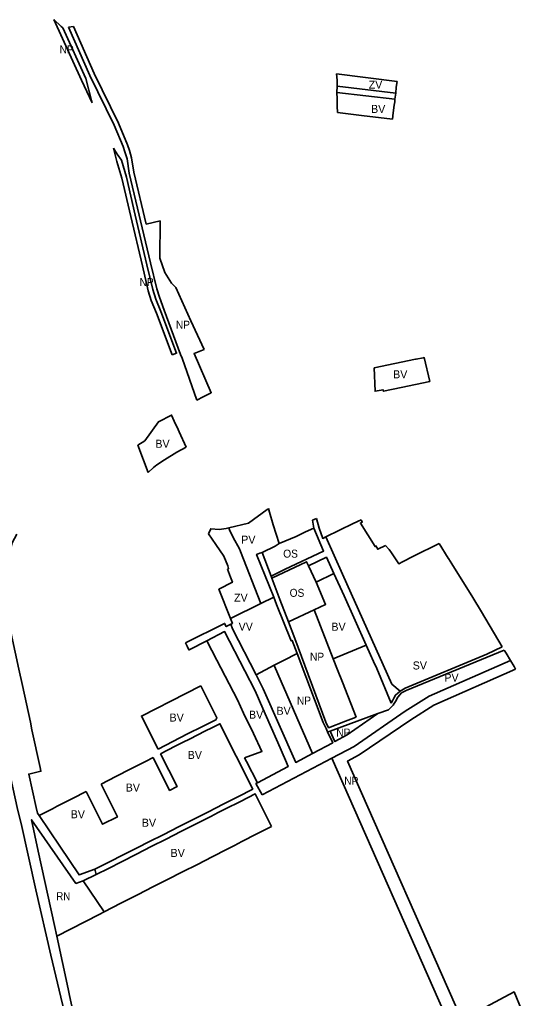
# Model space of a CAD drawing. Extents: x -650971 to -642489, y -1074311 to -1062745.
# Drawn here: x -648725 to -647975, y -1068126 to -1066658 of the extents above; entities that cross this region are included whole.
import ezdxf

# ---------------------------------------------------------------- set-up
doc = ezdxf.new("R2010")
doc.units = 0
doc.header["$LTSCALE"] = 4.8
for name, color, linetype, lineweight in [('15', 7, 'Continuous', 35), ('19', 7, 'Continuous', 35), ('3', 7, 'Continuous', 35), ('40', 7, 'Continuous', 35), ('45', 7, 'Continuous', 35), ('48', 7, 'Continuous', 35), ('62', 7, 'Continuous', 35), ('7', 7, 'Continuous', 35), ('9', 7, 'Continuous', 35)]:
    doc.layers.add(name, color=color, linetype=linetype, lineweight=lineweight)

msp = doc.modelspace()

# ---------------------------------------------------------------- linework, layer by layer
at = {"layer": '15'}
msp.add_lwpolyline([(-648248.77, -1066767.43), (-648248.43, -1066758.34), (-648160.51, -1066768.4), (-648161.58, -1066777.41)], close=True, dxfattribs=at)
for points in [[(-648410.92, -1067420.63), (-648381.48, -1067413.68), (-648353.35, -1067393.29), (-648352.16, -1067392.42), (-648351.06, -1067391.62)], [(-648351.06, -1067391.62), (-648349.67, -1067396.88), (-648344.41, -1067416.04), (-648335.38, -1067444.07)], [(-648347.51, -1067492.87), (-648326.09, -1067482.7), (-648268.67, -1067455.43), (-648283.21, -1067420.88), (-648285.08, -1067409.24), (-648279.24, -1067406.38)], [(-648279.24, -1067406.38), (-648275.41, -1067421.3), (-648270.02, -1067436.37), (-648265.197, -1067434.03)], [(-648362.585, -1067534.204), (-648393.17, -1067455.88), (-648394.92, -1067452.23), (-648404.29, -1067434.9), (-648409.61, -1067423.44), (-648410.92, -1067420.63)], [(-648728.95, -1067430.33), (-648735.59, -1067442.88), (-648748.53, -1067499.3), (-648751.29, -1067514.57), (-648731.06, -1067607.06), (-648725.8, -1067632.36), (-648720.1, -1067657.12), (-648708.26, -1067712.07), (-648706.08, -1067723.56)], [(-648265.197, -1067434.03), (-648240.51, -1067489.9), (-648166.173, -1067654.853), (-648153.98, -1067665.43)], [(-648335.38, -1067444.07), (-648341.15, -1067448.14), (-648361, -1067457.36), (-648364.19, -1067458.619)], [(-648580.062, -1068590.087), (-648579.97, -1068587.39), (-648566.33, -1068582.22), (-648561.032, -1068578.982), (-648572.95, -1068522.97), (-648573.96, -1068518.34), (-648594.38, -1068425.02), (-648615.87, -1068327.3), (-648634.84, -1068248.76), (-648655.88, -1068153.63), (-648662.71, -1068124.76), (-648677.61, -1068061.74), (-648700.16, -1067963.42), (-648722.09, -1067863.84), (-648727.05, -1067844.33), (-648738.7, -1067792.04), (-648749.97, -1067741.49), (-648767.84, -1067652.98), (-648791.68, -1067543.78), (-648792.97, -1067537.86), (-648804.08, -1067534.88), (-648813.94, -1067506.27), (-648827.86, -1067465.86)], [(-648364.19, -1067458.619), (-648369.01, -1067460.52), (-648343.409, -1067524.81), (-648362.585, -1067534.204)], [(-648253.1, -1067489.23), (-648264.34, -1067464.83), (-648291.17, -1067477.57)], [(-648291.17, -1067477.57), (-648291.172, -1067477.571), (-648294.04, -1067471.35), (-648346.27, -1067496.14), (-648347.51, -1067492.87)], [(-648204.88, -1067596.54), (-648237.81, -1067522.42), (-648253.1, -1067489.23)], [(-648475.78, -1067593.11), (-648417.19, -1067564.02), (-648414.73, -1067568.8), (-648408.002, -1067565.219)], [(-648408.002, -1067565.219), (-648405.054, -1067571.837), (-648369.949, -1067640.851)], [(-648367.811, -1067802.994), (-648321.623, -1067778.399), (-648326, -1067769), (-648337.32, -1067742.59), (-648348.55, -1067716.71), (-648359.6, -1067691.58), (-648371.34, -1067665.08), (-648386.91, -1067634.83), (-648417.12, -1067576.17), (-648443.83, -1067589.92), (-648470.47, -1067603.64)], [(-648470.47, -1067603.64), (-648470.57, -1067603.69), (-648473.34, -1067598.06), (-648475.78, -1067593.11)], [(-648167.48, -1067683.45), (-648189.03, -1067631.71), (-648193.8, -1067621), (-648198.39, -1067610.97), (-648204.88, -1067596.54)], [(-648187.139, -1067699.179), (-648171.21, -1067693.37), (-648164.09, -1067686.51), (-648162.69, -1067684), (-648161, -1067680.96), (-648157.2, -1067674.32), (-648151.6, -1067668.12), (-648144.83, -1067664.48), (-647997.681, -1067604.11)], [(-647997.681, -1067604.11), (-647995.04, -1067608.56), (-647988.334, -1067619.747)], [(-647988.334, -1067619.747), (-648110.36, -1067673.133), (-648146.127, -1067695.8), (-648222.872, -1067748.412), (-648256.499, -1067766.091), (-648360.993, -1067821.027)], [(-648369.949, -1067640.851), (-648359.213, -1067661.956), (-648310.511, -1067772.476), (-648285.254, -1067759.009)], [(-648153.98, -1067665.43), (-648160.68, -1067671.55), (-648163.11, -1067676.17), (-648164.79, -1067678.96), (-648167.48, -1067683.45)], [(-648258.96, -1067725.37), (-648251.711, -1067741.124), (-648233.264, -1067731.288), (-648187.139, -1067699.179)], [(-648706.08, -1067723.56), (-648693.78, -1067780.24), (-648692.53, -1067785.79), (-648704.614, -1067788.491), (-648710.96, -1067789.91), (-648699.593, -1067840.046)], [(-648285.254, -1067759.009), (-648255.016, -1067742.886), (-648262.632, -1067726.711), (-648262.63, -1067726.71), (-648258.96, -1067725.37)], [(-648360.993, -1067821.027), (-648370.113, -1067804.22), (-648367.811, -1067802.994)], [(-648699.593, -1067840.046), (-648699.621, -1067840.06), (-648697.7, -1067848.43), (-648695.27, -1067852.04)], [(-648629.22, -1067950.214), (-648640, -1067954), (-648706.687, -1067858.345), (-648696.93, -1067905.76), (-648672.31, -1068017.25), (-648668.92, -1068032.96)], [(-648695.27, -1067852.04), (-648664.41, -1067897.91), (-648635.249, -1067941.252), (-648611.61, -1067932.63), (-648609.91, -1067940.58), (-648629.22, -1067950.214)], [(-648668.92, -1068032.96), (-648651.89, -1068111.95), (-648649.74, -1068121.95), (-648644.73, -1068145.27), (-648630.99, -1068209.19), (-648610.14, -1068304.32), (-648587.39, -1068405.82), (-648559.91, -1068532.62), (-648551.041, -1068573.16)]]:
    msp.add_lwpolyline(points, dxfattribs=at)
at = {"layer": '19'}
for points in [[(-648265.197, -1067434.03), (-648224.19, -1067414.14), (-648212.32, -1067408.39)], [(-648212.32, -1067408.39), (-648211.08, -1067410.6), (-648210.48, -1067411.68), (-648213.34, -1067413.46), (-648191.46, -1067448.59), (-648190.23, -1067447.83), (-648187.44, -1067452.8), (-648175.94, -1067446.89)], [(-648153.98, -1067665.43), (-648166.173, -1067654.853), (-648240.51, -1067489.9), (-648265.197, -1067434.03)], [(-648175.94, -1067446.89), (-648171.21, -1067452.01), (-648170.38, -1067453.23), (-648166.97, -1067458.18), (-648155.85, -1067474.35), (-648150.46, -1067471.66)], [(-648150.46, -1067471.66), (-648133.56, -1067463.2), (-648095.28, -1067444.06)], [(-648095.28, -1067444.06), (-648081.69, -1067465.92), (-648081.31, -1067466.54), (-648076.32, -1067474.6), (-648045.04, -1067525.15), (-648031.77, -1067546.6), (-648000.63, -1067599.14)], [(-648000.63, -1067599.14), (-648023.96, -1067610.13), (-648146.21, -1067661.3), (-648153.98, -1067665.43)]]:
    msp.add_lwpolyline(points, dxfattribs=at)
at = {"layer": '3'}
for p, q in [((-648248.77, -1066767.43), (-648161.58, -1066777.41)), ((-648369.949, -1067640.851), (-648342.697, -1067626.806)), ((-648629.22, -1067950.214), (-648609.91, -1067940.58))]:
    msp.add_line(p, q, dxfattribs=at)
for points in [[(-648247.78, -1066797.53), (-648248.09, -1066787.96), (-648248.448, -1066777.212), (-648248.77, -1066767.43)], [(-648161.58, -1066777.41), (-648162.01, -1066781.79), (-648162.8, -1066786.8), (-648164.14, -1066797.98), (-648165.33, -1066807.74)], [(-648165.33, -1066807.74), (-648211.58, -1066802.18), (-648247.78, -1066797.53)], [(-648193.02, -1067180.66), (-648131.01, -1067167.84), (-648130.21, -1067167.7), (-648118.74, -1067165.43), (-648117.563, -1067165.191), (-648109.1, -1067201.21)], [(-648109.1, -1067201.21), (-648152.5, -1067210.23), (-648179, -1067215.71), (-648179.42, -1067213.37), (-648191.439, -1067215.62), (-648193.02, -1067180.66)], [(-648531.51, -1067337.57), (-648547.17, -1067296.68), (-648536.84, -1067290.29), (-648516.47, -1067261.54), (-648496.55, -1067251.53), (-648492.62, -1067260.53)], [(-648492.62, -1067260.53), (-648486.79, -1067273.26), (-648485.16, -1067276.83), (-648474.69, -1067299.66)], [(-648474.69, -1067299.66), (-648488.66, -1067307.11), (-648507.25, -1067318.35), (-648518.55, -1067326.3), (-648523.55, -1067330.33), (-648531.51, -1067337.57)], [(-648282.863, -1067543.596), (-648265.757, -1067535.555), (-648279.86, -1067502.11), (-648253.1, -1067489.23)], [(-648253.1, -1067489.23), (-648237.81, -1067522.42), (-648204.88, -1067596.54), (-648254.04, -1067616.96), (-648282.863, -1067543.596)], [(-648443.83, -1067589.92), (-648417.12, -1067576.17), (-648386.91, -1067634.83), (-648371.34, -1067665.08), (-648359.6, -1067691.58), (-648348.55, -1067716.71), (-648337.32, -1067742.59), (-648326, -1067769), (-648321.623, -1067778.399), (-648367.811, -1067802.994)], [(-648387.04, -1067765.67), (-648361.08, -1067755.88), (-648373.99, -1067728.95), (-648388.506, -1067698.645), (-648397.98, -1067678.79), (-648428.7, -1067619.24), (-648443.83, -1067589.92)], [(-648342.697, -1067626.806), (-648342.023, -1067628.096), (-648285.254, -1067759.009)], [(-648285.254, -1067759.009), (-648310.511, -1067772.476), (-648359.213, -1067661.956), (-648369.949, -1067640.851)], [(-648516.73, -1067752.57), (-648541.86, -1067702.86), (-648475.01, -1067668.94), (-648452.72, -1067657.62)], [(-648452.72, -1067657.62), (-648428.67, -1067705.52), (-648430.17, -1067708.33), (-648450.23, -1067718.32), (-648472.5, -1067729.76), (-648494.84, -1067741.06), (-648516.73, -1067752.57)], [(-648513.23, -1067759.38), (-648491.14, -1067748.02), (-648480.06, -1067742.47), (-648468.97, -1067736.91), (-648446.58, -1067725.71), (-648435.34, -1067720.01), (-648424.14, -1067714.34), (-648399.64, -1067763.26), (-648374.84, -1067812.43), (-648397.04, -1067823.85), (-648419.44, -1067835.3), (-648441.47, -1067846.37), (-648486.09, -1067868.98), (-648508.22, -1067880.38), (-648530.81, -1067891.61), (-648547.09, -1067899.87), (-648611.61, -1067932.63)], [(-648524.44, -1067765.11), (-648499.7, -1067814.37), (-648488.49, -1067808.76), (-648513.23, -1067759.38)], [(-648602.3, -1067804.83), (-648580.14, -1067793.61), (-648557.84, -1067782.26), (-648535.61, -1067770.85), (-648524.44, -1067765.11)], [(-648367.811, -1067802.994), (-648384.25, -1067771.07), (-648387.04, -1067765.67)], [(-648695.27, -1067852.04), (-648675.26, -1067841.84), (-648668.085, -1067838.186), (-648658.42, -1067833.26), (-648645.11, -1067826.48), (-648624.76, -1067816.11)], [(-648624.76, -1067816.11), (-648600.14, -1067865.29), (-648577.78, -1067854.07), (-648602.3, -1067804.83)], [(-648609.91, -1067940.58), (-648591.04, -1067931.62), (-648571.88, -1067921.71), (-648549.44, -1067910.07), (-648527.33, -1067898.74), (-648504.92, -1067887.52), (-648482.5, -1067876.22), (-648437.89, -1067853.4), (-648426.65, -1067847.64), (-648415.69, -1067841.98), (-648393.35, -1067830.81), (-648371.27, -1067819.47), (-648346.57, -1067868.56)], [(-648611.61, -1067932.63), (-648635.249, -1067941.252), (-648664.41, -1067897.91), (-648695.27, -1067852.04)], [(-648346.57, -1067868.56), (-648368.78, -1067879.75), (-648391.08, -1067891.24), (-648402.29, -1067897.02), (-648413.41, -1067902.53), (-648435.55, -1067913.84), (-648457.87, -1067925.4), (-648480.12, -1067936.55), (-648502.59, -1067948), (-648524.72, -1067958.93), (-648546.76, -1067970.44), (-648572.5, -1067983.59), (-648597.93, -1067996.72), (-648629.22, -1067950.214)]]:
    msp.add_lwpolyline(points, dxfattribs=at)
at = {"layer": '40'}
msp.add_line((-648249.44, -1066739.8), (-648158.49, -1066750.93), dxfattribs=at)
for points in [[(-648248.43, -1066758.34), (-648248.34, -1066749.33), (-648249.44, -1066739.8)], [(-648158.49, -1066750.93), (-648159.66, -1066759.8), (-648160.51, -1066768.4), (-648248.43, -1066758.34)], [(-648441.48, -1067429.63), (-648437.75, -1067421.99), (-648425, -1067423.05), (-648414.84, -1067421.56), (-648410.92, -1067420.63)], [(-648410.92, -1067420.63), (-648409.61, -1067423.44), (-648404.29, -1067434.9), (-648394.92, -1067452.23), (-648393.17, -1067455.88), (-648362.585, -1067534.204), (-648408.26, -1067556.58)], [(-648418.3, -1067462.86), (-648430.4, -1067445.51), (-648441.48, -1067429.63)], [(-648412.89, -1067482.55), (-648411.25, -1067481.73), (-648412.46, -1067477.42), (-648418.3, -1067462.86)], [(-648408.26, -1067556.58), (-648425.5, -1067512.73), (-648405.27, -1067502.27), (-648408.24, -1067494.59), (-648412.89, -1067482.55)]]:
    msp.add_lwpolyline(points, dxfattribs=at)
at = {"layer": '45'}
for points in [[(-648408.26, -1067556.58), (-648362.585, -1067534.205), (-648343.409, -1067524.81)], [(-648343.409, -1067524.81), (-648339.16, -1067535.48), (-648317.43, -1067590), (-648315.92, -1067589.37), (-648308.43, -1067609.15)], [(-648408.002, -1067565.219), (-648405.41, -1067563.84), (-648408.26, -1067556.58)], [(-648369.949, -1067640.851), (-648405.054, -1067571.837), (-648408.002, -1067565.219)], [(-648308.43, -1067609.15), (-648328.54, -1067619.51), (-648342.697, -1067626.806), (-648369.949, -1067640.851)]]:
    msp.add_lwpolyline(points, dxfattribs=at)
at = {"layer": '48'}
for p, q in [((-648651.1, -1066669.56), (-648643.925, -1066668.483)), ((-648258.96, -1067725.37), (-648187.139, -1067699.179))]:
    msp.add_line(p, q, dxfattribs=at)
for points in [[(-648673.407, -1066658.275), (-648662.46, -1066668.53), (-648659.95, -1066670.89), (-648625.44, -1066746.45)], [(-648615.972, -1066783.008), (-648631.791, -1066749.394), (-648673.407, -1066658.275)], [(-648458.73, -1067229.1), (-648480.57, -1067166.13), (-648483.31, -1067160.63), (-648507.88, -1067093.9), (-648514.86, -1067074.83), (-648518.72, -1067061.99), (-648528.01, -1067023.13), (-648560.2, -1066888.58), (-648563.48, -1066866.96), (-648566.63, -1066856.72), (-648569.13, -1066848.61), (-648582.52, -1066816.7), (-648619.11, -1066742.12), (-648651.1, -1066669.56)], [(-648643.925, -1066668.483), (-648612.763, -1066739.165), (-648576.145, -1066813.802), (-648562.542, -1066846.219), (-648559.94, -1066854.66), (-648556.637, -1066865.397), (-648553.323, -1066887.238), (-648534.701, -1066965.077), (-648513.842, -1066960.243)], [(-648625.44, -1066746.45), (-648616.86, -1066779.79), (-648615.972, -1066783.008)], [(-648583.94, -1066851.11), (-648577.99, -1066860.17), (-648571.96, -1066869.37)], [(-648495.63, -1067161.363), (-648519.471, -1067098.516), (-648526.988, -1067079.8), (-648531.681, -1067065.222), (-648540.476, -1067027.594), (-648557.816, -1066953.444), (-648571.167, -1066896.326), (-648578.702, -1066871.259), (-648583.94, -1066851.11)], [(-648571.96, -1066869.37), (-648564.4, -1066894.52), (-648551, -1066951.85), (-648533.66, -1067026), (-648524.93, -1067063.35), (-648520.4, -1067077.42), (-648512.95, -1067095.97), (-648489.1, -1067158.84), (-648495.63, -1067161.363)], [(-648513.842, -1066960.243), (-648514.38, -1067016.2), (-648506.78, -1067037.81), (-648496.87, -1067053.5), (-648490.23, -1067060.06), (-648467.56, -1067110.02), (-648447.66, -1067153.25)], [(-648447.66, -1067153.25), (-648462.97, -1067159.24), (-648437.02, -1067217.99), (-648449.03, -1067224.14), (-648458.73, -1067229.1)], [(-648321.361, -1067561.69), (-648282.863, -1067543.596), (-648254.04, -1067616.96)], [(-648219.86, -1067704.42), (-648235.78, -1067710.79), (-648261.25, -1067720.39), (-648265.08, -1067712.06), (-648311.95, -1067586.45), (-648321.361, -1067561.69)], [(-648342.697, -1067626.806), (-648328.54, -1067619.51), (-648308.43, -1067609.15)], [(-648308.43, -1067609.15), (-648269.27, -1067712.6), (-648264.949, -1067721.79), (-648262.63, -1067726.71)], [(-648285.254, -1067759.009), (-648342.023, -1067628.096), (-648342.697, -1067626.806)], [(-648256.499, -1067766.091), (-648222.872, -1067748.412), (-648146.127, -1067695.8), (-648110.36, -1067673.133), (-647988.334, -1067619.747)], [(-648254.04, -1067616.96), (-648247.53, -1067633.53), (-648240.19, -1067652.12), (-648219.86, -1067704.42)], [(-647988.334, -1067619.747), (-647982.95, -1067628.73), (-647980.561, -1067632.719)], [(-647980.561, -1067632.719), (-648103.298, -1067686.416), (-648137.869, -1067708.325), (-648215.115, -1067761.28), (-648232.676, -1067770.513), (-648061.329, -1068158.649), (-647982.969, -1068116.575), (-647971.35, -1068144.48), (-647929.45, -1068244.16)], [(-648187.139, -1067699.179), (-648233.264, -1067731.288), (-648251.711, -1067741.124), (-648258.96, -1067725.37)], [(-648262.63, -1067726.71), (-648262.632, -1067726.711), (-648255.016, -1067742.886), (-648285.254, -1067759.009)], [(-648165.28, -1068214.465), (-648079.002, -1068168.139), (-648256.499, -1067766.091)]]:
    msp.add_lwpolyline(points, dxfattribs=at)
at = {"layer": '7'}
for points in [[(-648668.92, -1068032.96), (-648672.31, -1068017.25), (-648696.93, -1067905.76), (-648706.687, -1067858.345), (-648640, -1067954), (-648629.22, -1067950.214), (-648597.93, -1067996.72)], [(-648597.93, -1067996.72), (-648605.323, -1068000.463), (-648668.92, -1068032.96)]]:
    msp.add_lwpolyline(points, dxfattribs=at)
at = {"layer": '9'}
for points in [[(-648283.21, -1067420.88), (-648268.67, -1067455.43), (-648326.09, -1067482.7), (-648347.51, -1067492.87), (-648361, -1067457.36)], [(-648335.38, -1067444.07), (-648309.57, -1067433.34), (-648295.66, -1067426.76), (-648283.21, -1067420.88)], [(-648361, -1067457.36), (-648341.15, -1067448.14), (-648335.38, -1067444.07)], [(-648346.27, -1067496.14), (-648294.04, -1067471.35), (-648291.172, -1067477.571), (-648291.17, -1067477.57), (-648279.86, -1067502.11)], [(-648321.361, -1067561.69), (-648334.09, -1067528.2), (-648346.27, -1067496.14)], [(-648279.86, -1067502.11), (-648265.757, -1067535.555), (-648282.863, -1067543.596), (-648321.361, -1067561.69)]]:
    msp.add_lwpolyline(points, dxfattribs=at)

# ---------------------------------------------------------------- texts
at = {"layer": '62'}
for s, width, p in [('NP', 0.95, (-648664.583, -1066709.041)), ('NP', 0.95, (-648544.583, -1067058.041)), ('NP', 0.95, (-648490.15, -1067121.972)), ('OS', 0.95, (-648329.213, -1067465.317)), ('OS', 0.95, (-648319.549, -1067524.064)), ('NP', 0.95, (-648289.019, -1067619.94)), ('NP', 0.95, (-648308.631, -1067685.579)), ('NP', 0.95, (-648249.631, -1067733.579)), ('NP', 0.95, (-648237.583, -1067806.041)), ('RN', 0.9, (-648669.473, -1067979.058))]:
    msp.add_text(s, height=12, dxfattribs=dict(at, width=width)).set_placement(p)
for s, p in [('ZV', (-648201.026, -1066761.906)), ('BV', (-648197.475, -1066798.284)), ('BV', (-648164.386, -1067196.331)), ('BV', (-648520.956, -1067300.498)), ('PV', (-648392.213, -1067444.317)), ('ZV', (-648402.918, -1067531.307)), ('VV', (-648396.075, -1067574.614)), ('BV', (-648256.942, -1067574.923)), ('SV', (-648135.028, -1067633.035)), ('PV', (-648087.517, -1067651.275)), ('BV', (-648499.724, -1067711.153)), ('BV', (-648380.551, -1067706.775)), ('BV', (-648339.301, -1067701.063)), ('BV', (-648472.48, -1067767.243)), ('BV', (-648565.429, -1067816.121)), ('BV', (-648647.961, -1067856.185)), ('BV', (-648541.281, -1067868.87)), ('BV', (-648498.112, -1067914.191))]:
    msp.add_text(s, height=12, dxfattribs=at).set_placement(p)

doc.saveas('drawing.dxf')
